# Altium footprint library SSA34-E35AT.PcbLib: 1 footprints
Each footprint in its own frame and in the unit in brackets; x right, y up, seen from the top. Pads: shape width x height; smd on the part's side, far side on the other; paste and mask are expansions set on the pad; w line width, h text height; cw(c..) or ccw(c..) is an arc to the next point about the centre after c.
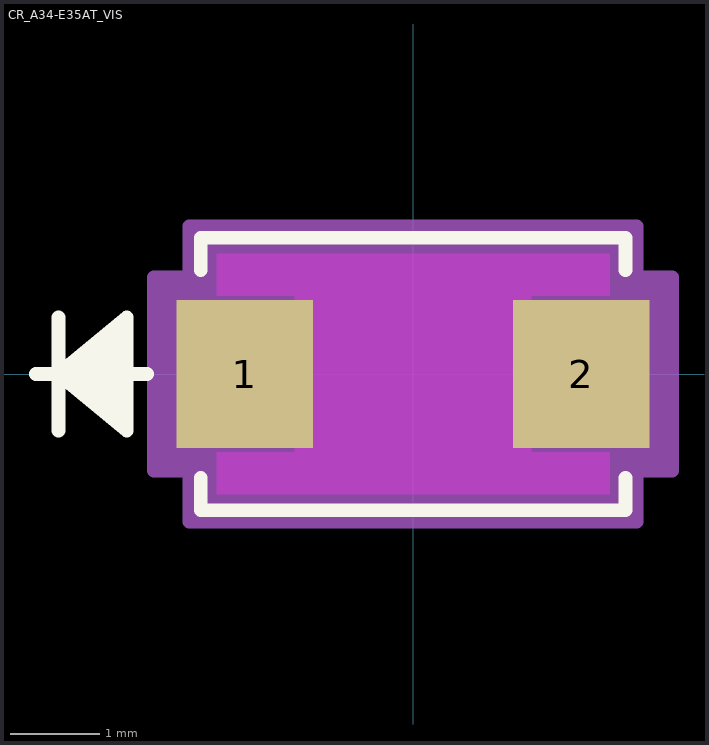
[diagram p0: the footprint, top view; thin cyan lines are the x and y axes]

## CR_A34-E35AT_VIS [mil]
pads (2):
  rect 60x65 smd paste+0 mask+0: 1(-74.02,0) 2(74.02,0)
Top Layer keep-out:
  region: -52.02,-34.5 -52.02,34.5 52.02,34.5 52.02,-34.5
  region: -86.5,34.5 -86.5,53 86.5,53 86.5,34.5
  region: -86.5,-53 -86.5,-34.5 86.5,-34.5 86.5,-53
Top Overlay:
  lines w6: -166.02,0 -117.12,0 ; -156.02,-25 -156.02,25 ; -126.02,-20 -156.02,0 ; -126.02,-15 -156.02,0 ; -126.02,-10 -156.02,0 ; -126.02,-5 -156.02,0 ; -126.02,5 -156.02,0 ; -126.02,10 -156.02,0 ; -126.02,15 -156.02,0 ; -126.02,20 -156.02,0 ; -93.5,-45.6 -93.5,-60 93.5,-60 93.5,-45.6 ; -93.5,45.6 -93.5,60 93.5,60 93.5,45.6 ; -156.02,0 -126.02,25 -126.02,-25 -156.02,0
  text ".Designator" at -137.5,-25 h50
Mechanical 13:
  lines w1: -166.02,0 -116.02,0 ; -156.02,-25 -156.02,25 ; -126.02,-20 -156.02,0 ; -126.02,-15 -156.02,0 ; -126.02,-10 -156.02,0 ; -126.02,-5 -156.02,0 ; -126.02,5 -156.02,0 ; -126.02,10 -156.02,0 ; -126.02,15 -156.02,0 ; -126.02,20 -156.02,0 ; -156.02,0 -126.02,25 -126.02,-25 -156.02,0 ; -88.5,-55 88.5,-55 88.5,55 -88.5,55 -88.5,-55
  text ".Designator" at -137.5,-25 h50
Mechanical 15:
  region: -98.5,-42.5 -114.02,-42.5 -114.02,42.5 -98.5,42.5 -98.5,65 98.5,65 98.5,42.5 114.02,42.5 114.02,-42.5 98.5,-42.5 98.5,-65 -98.5,-65
  lines w6: -114.02,-42.5 -114.02,42.5 -98.5,42.5 -98.5,65 98.5,65 98.5,42.5 114.02,42.5 114.02,-42.5 98.5,-42.5 98.5,-65 -98.5,-65 -98.5,-42.5 -114.02,-42.5
3D body "CR_A34-E35AT_VIS.step": height 92.01, standoff 0, extent -88.5,-55 88.5,55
